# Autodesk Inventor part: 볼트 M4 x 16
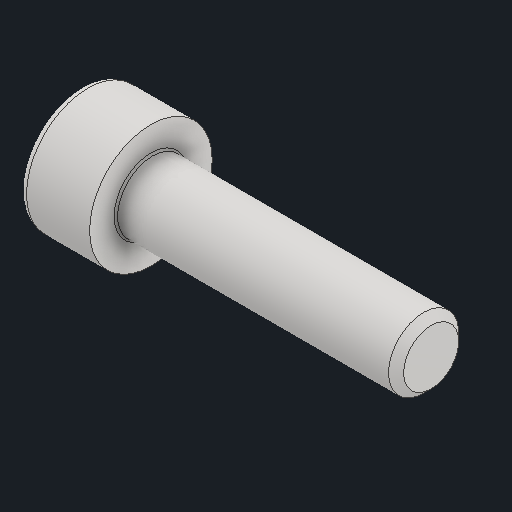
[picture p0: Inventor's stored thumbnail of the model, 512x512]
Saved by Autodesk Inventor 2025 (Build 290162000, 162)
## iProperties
Created: 2025-08
Part Number: 볼트 M4 x 16
Material: 스테인리스강
Description: 6각 소켓 머리 캡 나사
Document SubType Name: Modeling
Designer: infra10
Density: 8.08 g/cm^3
Appearance: 기본값
Author: jhkim
Sending System: Autodesk Inventor 2026
Preprocessor: ST-DEVELOPER v20.1
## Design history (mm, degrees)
feature "Solid1"
node "솔리드1"
